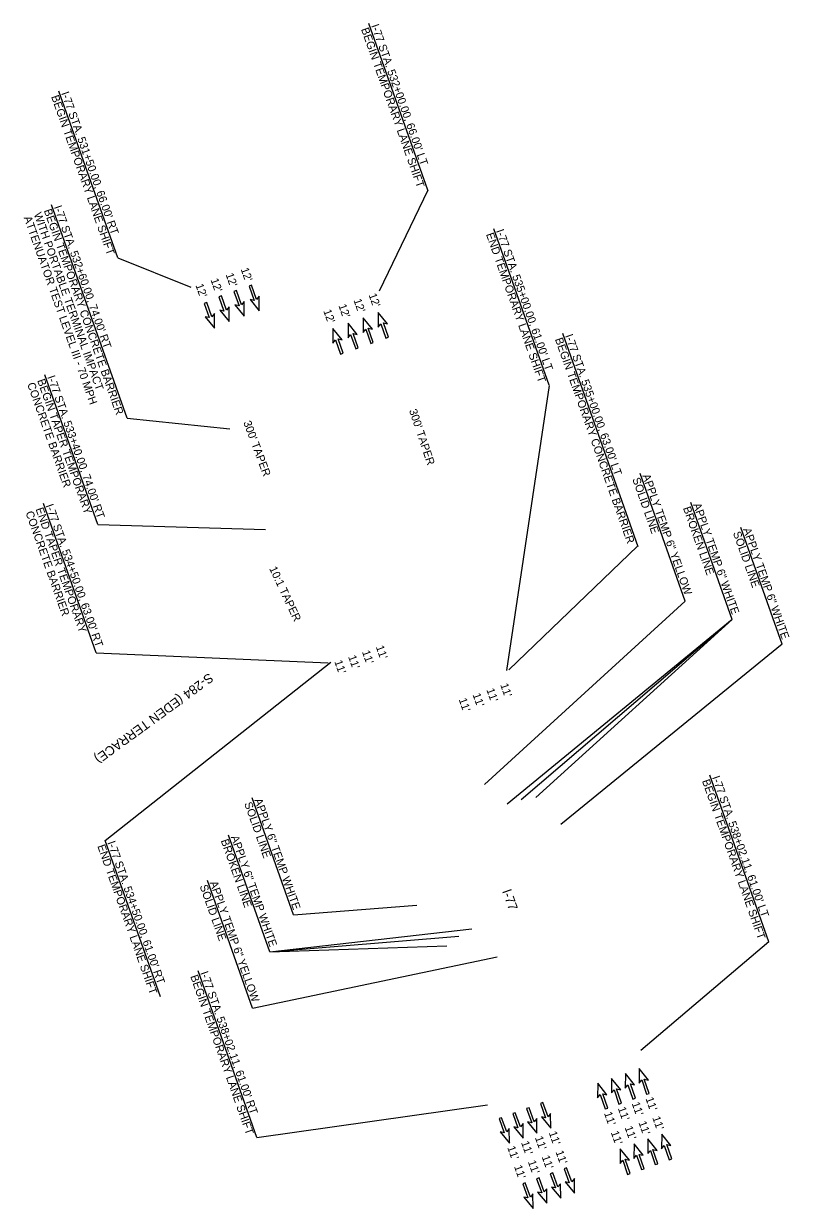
# Model space of a CAD drawing. Extents: x 2004770 to 2007199, y 1133765 to 1140032.
# Drawn here: x 2004770 to 2005344, y 1139147 to 1140032 of the extents above; entities that cross this region are included whole.
import ezdxf

# ---------------------------------------------------------------- set-up
doc = ezdxf.new("R2010")
doc.units = 0
doc.layers.add('RD_PD_MedBWall', color=7, linetype='Continuous')
doc.layers.add('RD_XS_Base', color=7, linetype='Continuous')

msp = doc.modelspace()

# ---------------------------------------------------------------- linework, layer by layer
at = {"layer": 'RD_PD_MedBWall'}
for p, q in [((2005072.66, 1139906.79), (2005028.47, 1140031.7)), ((2004840.37, 1139856.2), (2004796.18, 1139981.11)), ((2004847.21, 1139736), (2004790.68, 1139895.78)), ((2005163.62, 1139760.71), (2005122.15, 1139877.94)), ((2005230.34, 1139639.49), (2005173.82, 1139799.28)), ((2004825.37, 1139656.2), (2004785.7, 1139768.33)), ((2005265.62, 1139598.78), (2005231.79, 1139694.42)), ((2004824.17, 1139559.83), (2004784.51, 1139671.95)), ((2005300.81, 1139585.05), (2005269.81, 1139672.67)), ((2005338.27, 1139566.43), (2005307.28, 1139654.04)), ((2005300.81, 1139585.05), (2005132.04, 1139446.41)), ((2005300.81, 1139585.05), (2005142.55, 1139449.68)), ((2005328.25, 1139343.24), (2005284.06, 1139468.15)), ((2004971.9, 1139363.61), (2004940.91, 1139451.22)), ((2004872.3, 1139302.08), (2004830.83, 1139419.3)), ((2004954.34, 1139335.75), (2004923.34, 1139423.37)), ((2004941.34, 1139293.6), (2004907.5, 1139389.25)), ((2004954.34, 1139335.75), (2005095.94, 1139347.58)), ((2004954.34, 1139335.75), (2005086.82, 1139340.37)), ((2004944.63, 1139196.7), (2004900.44, 1139321.61))]:
    msp.add_line(p, q, dxfattribs=at)
for points in [[(2005072.66, 1139906.79), (2005036.27, 1139831.08)], [(2004840.37, 1139856.2), (2004895.15, 1139834.19)], [(2005163.7, 1139760.46), (2005131.61, 1139546.59)], [(2004847.21, 1139736), (2004924.29, 1139727.82)], [(2004825.37, 1139656.2), (2004950.97, 1139652.4)], [(2005229.92, 1139639.9), (2005133.49, 1139547.26)], [(2005265.62, 1139598.78), (2005115.17, 1139461.13)], [(2005300.81, 1139585.05), (2005153.57, 1139451.51)], [(2004824.17, 1139559.83), (2004998.03, 1139552.37)], [(2005338.27, 1139566.43), (2005172.38, 1139431.33)], [(2004830.83, 1139419.3), (2004999.92, 1139553.04)], [(2004971.9, 1139363.61), (2005064.37, 1139370.84)], [(2004954.34, 1139335.75), (2005105.64, 1139353.12)], [(2005328.25, 1139343.24), (2005232.36, 1139261.77)], [(2004941.34, 1139293.6), (2005124.73, 1139332.16)], [(2004944.63, 1139196.7), (2005117.35, 1139221.09)]]:
    msp.add_lwpolyline(points, dxfattribs=at)
for points in [[(2004940.57, 1139835.52), (2004938.69, 1139834.85), (2004942.47, 1139824.17), (2004939.4, 1139824.85), (2004946.3, 1139816.33), (2004946.31, 1139827.29), (2004944.35, 1139824.83)], [(2004917.95, 1139827.51), (2004916.06, 1139826.85), (2004919.84, 1139816.16), (2004916.77, 1139816.84), (2004923.67, 1139808.33), (2004923.69, 1139819.29), (2004921.73, 1139816.83)], [(2004929.26, 1139831.52), (2004927.38, 1139830.85), (2004931.15, 1139820.16), (2004928.08, 1139820.85), (2004934.99, 1139812.33), (2004935, 1139823.29), (2004933.04, 1139820.83)], [(2004907, 1139822.6), (2004905.11, 1139821.94), (2004908.89, 1139811.25), (2004905.82, 1139811.93), (2004912.73, 1139803.42), (2004912.74, 1139814.38), (2004910.78, 1139811.92)], [(2005018.61, 1139787.93), (2005020.5, 1139788.6), (2005016.72, 1139799.28), (2005019.79, 1139798.6), (2005012.88, 1139807.12), (2005012.87, 1139796.16), (2005014.83, 1139798.62)], [(2005029.92, 1139791.93), (2005031.81, 1139792.6), (2005028.03, 1139803.29), (2005031.1, 1139802.6), (2005024.2, 1139811.12), (2005024.19, 1139800.16), (2005026.14, 1139802.62)], [(2005041.24, 1139795.94), (2005043.12, 1139796.6), (2005039.34, 1139807.29), (2005042.41, 1139806.61), (2005035.51, 1139815.12), (2005035.5, 1139804.16), (2005037.46, 1139806.62)], [(2005007.3, 1139783.93), (2005009.18, 1139784.6), (2005005.4, 1139795.28), (2005008.47, 1139794.6), (2005001.57, 1139803.12), (2005001.56, 1139792.15), (2005003.52, 1139794.61)], [(2005215.98, 1139221.68), (2005217.87, 1139222.33), (2005214.19, 1139233.05), (2005217.25, 1139232.34), (2005210.43, 1139240.92), (2005210.32, 1139229.96), (2005212.3, 1139232.4)], [(2005226.35, 1139225.35), (2005228.24, 1139226), (2005224.56, 1139236.72), (2005227.62, 1139236.01), (2005220.8, 1139244.59), (2005220.69, 1139233.63), (2005222.67, 1139236.07)], [(2005236.72, 1139229.02), (2005238.61, 1139229.67), (2005234.93, 1139240.39), (2005237.99, 1139239.68), (2005231.17, 1139248.26), (2005231.06, 1139237.3), (2005233.04, 1139239.74)], [(2005205.61, 1139218.02), (2005207.5, 1139218.66), (2005203.82, 1139229.38), (2005206.88, 1139228.67), (2005200.06, 1139237.25), (2005199.95, 1139226.29), (2005201.93, 1139228.73)], [(2005158.93, 1139222.71), (2005157.05, 1139222.02), (2005160.93, 1139211.37), (2005157.85, 1139212.03), (2005164.83, 1139203.57), (2005164.74, 1139214.54), (2005162.81, 1139212.06)], [(2005138.26, 1139215.18), (2005136.38, 1139214.49), (2005140.26, 1139203.84), (2005137.18, 1139204.5), (2005144.16, 1139196.04), (2005144.07, 1139207.01), (2005142.14, 1139204.53)], [(2005148.59, 1139218.94), (2005146.72, 1139218.26), (2005150.59, 1139207.61), (2005147.52, 1139208.26), (2005154.5, 1139199.81), (2005154.41, 1139210.77), (2005152.47, 1139208.29)], [(2005127.92, 1139211.41), (2005126.04, 1139210.73), (2005129.92, 1139200.08), (2005126.85, 1139200.73), (2005133.83, 1139192.28), (2005133.74, 1139203.24), (2005131.8, 1139200.76)], [(2005253.58, 1139179.9), (2005255.48, 1139180.55), (2005251.8, 1139191.27), (2005254.86, 1139190.56), (2005248.03, 1139199.14), (2005247.92, 1139188.18), (2005249.9, 1139190.62)], [(2005222.48, 1139168.9), (2005224.37, 1139169.55), (2005220.69, 1139180.27), (2005223.75, 1139179.56), (2005216.93, 1139188.14), (2005216.81, 1139177.17), (2005218.79, 1139179.62)], [(2005232.85, 1139172.57), (2005234.74, 1139173.22), (2005231.06, 1139183.93), (2005234.12, 1139183.22), (2005227.3, 1139191.81), (2005227.18, 1139180.84), (2005229.16, 1139183.29)], [(2005243.21, 1139176.24), (2005245.11, 1139176.88), (2005241.43, 1139187.6), (2005244.49, 1139186.89), (2005237.66, 1139195.47), (2005237.55, 1139184.51), (2005239.53, 1139186.95)], [(2005166.37, 1139170.14), (2005164.49, 1139169.46), (2005168.36, 1139158.81), (2005165.29, 1139159.46), (2005172.27, 1139151.01), (2005172.18, 1139161.97), (2005170.24, 1139159.5)], [(2005176.7, 1139173.91), (2005174.82, 1139173.22), (2005178.7, 1139162.58), (2005175.62, 1139163.23), (2005182.61, 1139154.77), (2005182.52, 1139165.74), (2005180.58, 1139163.26)], [(2005145.69, 1139162.62), (2005143.81, 1139161.93), (2005147.69, 1139151.28), (2005144.62, 1139151.94), (2005151.6, 1139143.48), (2005151.51, 1139154.45), (2005149.57, 1139151.97)], [(2005156.03, 1139166.38), (2005154.15, 1139165.7), (2005158.03, 1139155.05), (2005154.95, 1139155.7), (2005161.93, 1139147.25), (2005161.84, 1139158.21), (2005159.91, 1139155.73)]]:
    msp.add_lwpolyline(points, close=True, dxfattribs=at)

# ---------------------------------------------------------------- texts
for s, rotation, p in [('BEGIN TEMPORARY LANE SHIFT', 289.48201, (2005022.53, 1140027.48)), ("I-77 STA. 532+00.00, 66.00' LT", 289.48201, (2005030.08, 1140030.15)), ('BEGIN TEMPORARY LANE SHIFT', 289.48201, (2004790.25, 1139976.89)), ("I-77 STA. 531+50.00, 66.00' RT", 289.48201, (2004797.79, 1139979.56)), ("I-77 STA. 532+60.00, 74.00' RT", 289.48201, (2004792.29, 1139894.23)), ('ATTENUATOR TEST LEVEL III - 70 MPH', 289.48201, (2004769.66, 1139886.23)), ('WITH PORTABLE TERMINAL IMPACT', 289.48201, (2004777.21, 1139888.9)), ('BEGIN TEMPORARY CONCRETE BARRIER', 289.48201, (2004784.75, 1139891.56)), ("I-77 STA. 535+00.00, 61.00' LT", 289.48201, (2005123.76, 1139876.39)), ('END TEMPORARY LANE SHIFT', 289.48201, (2005116.21, 1139873.72)), ("12'", 289.48201, (2004921.03, 1139843.61)), ("12'", 289.48201, (2004932.34, 1139847.61)), ("12'", 289.48201, (2004898.4, 1139835.61)), ("12'", 289.48201, (2004909.72, 1139839.61)), ("12'", 289.48201, (2005016.88, 1139824.35)), ("12'", 289.48201, (2005028.2, 1139828.35)), ("12'", 289.48201, (2004994.26, 1139816.34)), ("12'", 289.48201, (2005005.57, 1139820.34)), ("I-77 STA. 535+00.00, 63.00' LT", 289.48201, (2005175.43, 1139797.72)), ('BEGIN TEMPORARY CONCRETE BARRIER', 289.48201, (2005167.89, 1139795.06)), ('CONCRETE BARRIER', 289.48201, (2004772.23, 1139761.44)), ('BEGIN TAPER TEMPORARY', 289.48201, (2004779.77, 1139764.11)), ("I-77 STA. 533+40.00, 74.00' RT", 289.48201, (2004787.31, 1139766.78)), ("300' TAPER", 288.52717, (2005058.53, 1139741.65)), ("300' TAPER", 290.43685, (2004934.28, 1139732.7)), ('SOLID LINE', 289.48201, (2005225.86, 1139690.2)), ('APPLY TEMP 6" YELLOW', 289.48201, (2005233.4, 1139692.87)), ('CONCRETE BARRIER', 289.48201, (2004771.03, 1139665.07)), ('END TAPER TEMPORARY', 289.48201, (2004778.58, 1139667.73)), ("I-77 STA. 534+50.00, 63.00' RT", 289.48201, (2004786.12, 1139670.4)), ('BROKEN LINE', 289.48201, (2005263.88, 1139668.45)), ('APPLY TEMP 6" WHITE', 289.48201, (2005271.42, 1139671.11)), ('SOLID LINE', 289.48201, (2005301.35, 1139649.82)), ('APPLY TEMP 6" WHITE', 289.48201, (2005308.89, 1139652.49)), ('10:1 TAPER', 295.1926, (2004953.63, 1139623.15)), ("11'", 289.48201, (2005023.25, 1139560.75)), ("11'", 289.48201, (2005033.62, 1139564.42)), ("11'", 289.48201, (2005002.51, 1139553.41)), ("11'", 289.48201, (2005012.88, 1139557.08)), ("11'", 289.48201, (2005116.51, 1139532.32)), ("11'", 289.48201, (2005126.88, 1139535.98)), ("11'", 289.48201, (2005095.77, 1139524.98)), ("11'", 289.48201, (2005106.14, 1139528.65)), ('BEGIN TEMPORARY LANE SHIFT', 289.48201, (2005278.12, 1139463.93)), ("I-77 STA. 538+02.11, 61.00' LT", 289.48201, (2005285.67, 1139466.6)), ('SOLID LINE', 289.48201, (2004934.97, 1139447)), ('APPLY 6" TEMP WHITE', 289.48201, (2004942.52, 1139449.67)), ("I-77 STA. 534+50.00, 61.00' RT", 289.48201, (2004832.44, 1139417.75)), ('BROKEN LINE', 289.48201, (2004917.41, 1139419.15)), ('APPLY 6" TEMP WHITE', 289.48201, (2004924.95, 1139421.82)), ('END TEMPORARY LANE SHIFT', 289.48201, (2004824.89, 1139415.08)), ('SOLID LINE', 289.48201, (2004901.57, 1139385.03)), ('APPLY TEMP 6" YELLOW', 289.48201, (2004909.11, 1139387.69)), ("I-77 STA. 538+02.11, 61.00' RT", 289.48201, (2004902.05, 1139320.06)), ('BEGIN TEMPORARY LANE SHIFT', 289.48201, (2004894.51, 1139317.39)), ("11'", 289.48201, (2005225.43, 1139222.14)), ("11'", 289.48201, (2005235.8, 1139225.8)), ("11'", 289.48201, (2005204.69, 1139214.8)), ("11'", 289.48201, (2005215.06, 1139218.47)), ("11'", 289.48201, (2005220.14, 1139204.11)), ("11'", 289.48201, (2005230.51, 1139207.78)), ("11'", 289.48201, (2005240.88, 1139211.44)), ("11'", 289.48201, (2005152.9, 1139196.48)), ("11'", 289.48201, (2005163.27, 1139200.15)), ("11'", 289.48201, (2005209.77, 1139200.44)), ("11'", 289.48201, (2005132.16, 1139189.14)), ("11'", 289.48201, (2005142.53, 1139192.81)), ("11'", 289.48201, (2005147.61, 1139178.45)), ("11'", 289.48201, (2005157.98, 1139182.12)), ("11'", 289.48201, (2005168.35, 1139185.79)), ("11'", 289.48201, (2005137.24, 1139174.78))]:
    msp.add_text(s, height=6, rotation=rotation, dxfattribs=at).set_placement(p)
at = {"layer": 'RD_XS_Base'}
for s, rotation, p in [('S-284 (EDEN TERRACE)', 216.10226, (2004908.65, 1139545.18)), ('I-77', 289.48201, (2005128.33, 1139381.33))]:
    msp.add_text(s, height=7, rotation=rotation, dxfattribs=at).set_placement(p)

doc.saveas('drawing.dxf')
